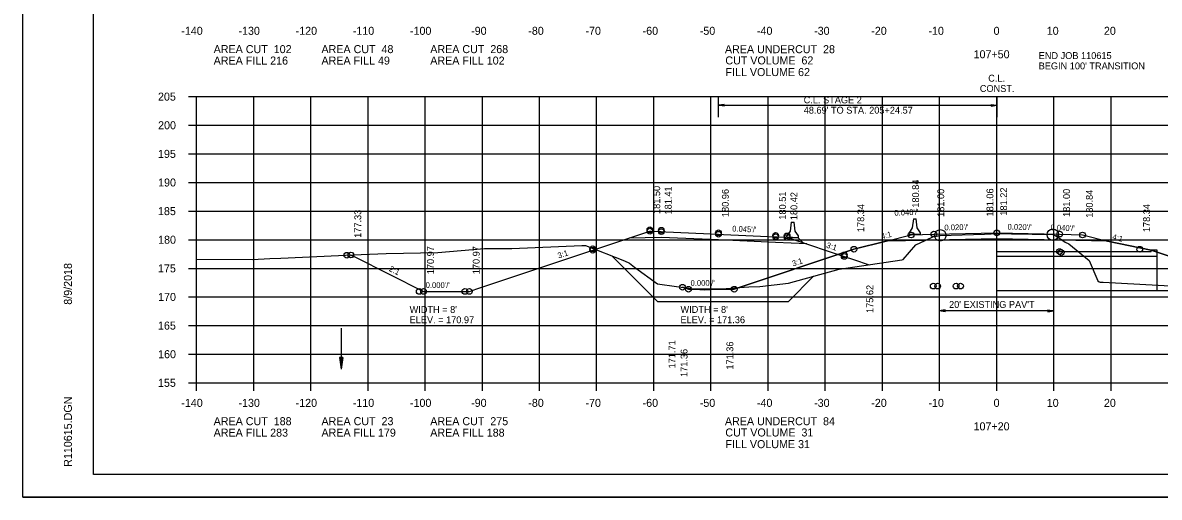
# Model space of a CAD drawing. Extents: x 1372132 to 1372465, y 380083 to 381790.
# Drawn here: x 1372131.6 to 1372330.4, y 380936.8 to 381019.7 of the extents above; entities that cross this region are included whole.
import ezdxf

# ---------------------------------------------------------------- set-up
doc = ezdxf.new("R2010")
doc.units = 0
for name, color, linetype in [('Default', 7, 'Continuous'), ('R_Alt Surface', 7, 'Continuous'), ('R_Axis', 7, 'Continuous'), ('R_Axis Annot', 7, 'Continuous'), ('R_Border', 7, 'Continuous'), ('R_Dimension', 7, 'Continuous'), ('R_Draft', 7, 'Continuous'), ('R_Erosion', 7, 'Continuous'), ('R_Exist Surface', 7, 'Continuous'), ('R_Fin Surface', 7, 'Continuous'), ('R_Grid', 7, 'Continuous'), ('R_No Plot', 7, 'Continuous'), ('R_Xsect Elev', 7, 'Continuous'), ('R_Xsect Slope', 7, 'Continuous')]:
    doc.layers.add(name, color=color, linetype=linetype)

msp = doc.modelspace()

# ---------------------------------------------------------------- linework, layer by layer
at = {"layer": 'Default'}
for p, q in [((1372329.04, 380979.74), (1372302.01, 380979.71)), ((1372329.04, 380979.74), (1372329.04, 380979.99)), ((1372330.04, 380979.99), (1372329.04, 380979.99)), ((1372330.04, 380972.9), (1372330.04, 380979.99)), ((1372330.04, 380978.9), (1372302.01, 380978.88)), ((1372344.25, 380972.92), (1372302.01, 380972.88))]:
    msp.add_line(p, q, dxfattribs=at)
at = {"layer": 'R_Alt Surface'}
for points in [[(1372268.79, 380981.09), (1372263.32, 380981.34), (1372253.32, 380981.79), (1372243.32, 380982.24), (1372237.72, 380982.12)], [(1372321.38, 380981.57), (1372313.01, 380981.74), (1372302.01, 380981.96), (1372291.01, 380981.74), (1372282.65, 380981.57)]]:
    msp.add_lwpolyline(points, dxfattribs=at)
at = {"layer": 'R_Axis'}
for p, q in [((1372160.61, 381006.83), (1372162.01, 381006.83)), ((1372162.01, 380956.83), (1372162.01, 381006.83)), ((1372160.61, 381001.83), (1372162.01, 381001.83)), ((1372160.61, 380996.83), (1372162.01, 380996.83)), ((1372160.61, 380991.83), (1372162.01, 380991.83)), ((1372160.61, 380986.83), (1372162.01, 380986.83)), ((1372160.61, 380981.83), (1372162.01, 380981.83)), ((1372160.61, 380976.83), (1372162.01, 380976.83)), ((1372160.61, 380971.83), (1372162.01, 380971.83)), ((1372160.61, 380966.83), (1372162.01, 380966.83)), ((1372160.61, 380961.83), (1372162.01, 380961.83)), ((1372160.61, 380956.83), (1372162.01, 380956.83)), ((1372162.01, 380956.83), (1372442.01, 380956.83)), ((1372162.01, 380955.43), (1372162.01, 380956.83)), ((1372172.01, 380955.43), (1372172.01, 380956.83)), ((1372182.01, 380955.43), (1372182.01, 380956.83)), ((1372192.01, 380955.43), (1372192.01, 380956.83)), ((1372202.01, 380955.43), (1372202.01, 380956.83)), ((1372212.01, 380955.43), (1372212.01, 380956.83)), ((1372222.01, 380955.43), (1372222.01, 380956.83)), ((1372232.01, 380955.43), (1372232.01, 380956.83)), ((1372242.01, 380955.43), (1372242.01, 380956.83)), ((1372252.01, 380955.43), (1372252.01, 380956.83)), ((1372262.01, 380955.43), (1372262.01, 380956.83)), ((1372272.01, 380955.43), (1372272.01, 380956.83)), ((1372282.01, 380955.43), (1372282.01, 380956.83)), ((1372292.01, 380955.43), (1372292.01, 380956.83)), ((1372302.01, 380955.43), (1372302.01, 380956.83)), ((1372312.01, 380955.43), (1372312.01, 380956.83)), ((1372322.01, 380955.43), (1372322.01, 380956.83))]:
    msp.add_line(p, q, dxfattribs=at)
at = {"layer": 'R_Border'}
for p, q in [((1372144.01, 380940.83), (1372144.01, 381146.29)), ((1372144.01, 380940.83), (1372144.01, 380940.83)), ((1372460.19, 380940.83), (1372144.01, 380940.83))]:
    msp.add_line(p, q, dxfattribs=at)
at = {"layer": 'R_Dimension'}
for p, q in [((1372187.03, 380961.23), (1372187.33, 380959.23)), ((1372187.63, 380961.23), (1372187.03, 380961.23)), ((1372187.03, 380961.23), (1372187.33, 380959.23)), ((1372187.63, 380961.23), (1372187.03, 380961.23)), ((1372187.08, 380961.23), (1372187.33, 380959.56)), ((1372187.08, 380961.23), (1372187.33, 380959.56)), ((1372187.13, 380961.23), (1372187.33, 380959.91)), ((1372187.13, 380961.23), (1372187.33, 380959.91)), ((1372187.18, 380961.23), (1372187.33, 380960.24)), ((1372187.18, 380961.23), (1372187.33, 380960.24)), ((1372187.23, 380961.23), (1372187.33, 380960.58)), ((1372187.23, 380961.23), (1372187.33, 380960.58)), ((1372187.28, 380961.23), (1372187.33, 380960.91)), ((1372187.28, 380961.23), (1372187.33, 380960.91)), ((1372187.63, 380961.23), (1372187.33, 380959.23)), ((1372187.43, 380961.23), (1372187.33, 380960.58)), ((1372187.53, 380961.23), (1372187.33, 380959.91)), ((1372187.58, 380961.23), (1372187.33, 380959.56)), ((1372187.48, 380961.23), (1372187.33, 380960.24)), ((1372187.38, 380961.23), (1372187.33, 380960.91)), ((1372187.63, 380961.23), (1372187.33, 380959.23)), ((1372187.43, 380961.23), (1372187.33, 380960.58)), ((1372187.53, 380961.23), (1372187.33, 380959.91)), ((1372187.58, 380961.23), (1372187.33, 380959.56)), ((1372187.48, 380961.23), (1372187.33, 380960.24)), ((1372187.38, 380961.23), (1372187.33, 380960.91))]:
    msp.add_line(p, q, dxfattribs=at)
at = {"layer": 'R_Draft'}
for p, q in [((1372253.32, 381003.23), (1372253.32, 381006.83)), ((1372302.01, 381006.83), (1372302.01, 381003.23)), ((1372254.32, 381005.46), (1372253.32, 381005.31)), ((1372253.32, 381005.31), (1372302.01, 381005.31)), ((1372254.32, 381005.16), (1372253.32, 381005.31)), ((1372254.32, 381005.44), (1372253.49, 381005.31)), ((1372254.32, 381005.19), (1372253.49, 381005.31)), ((1372254.32, 381005.41), (1372253.66, 381005.31)), ((1372254.32, 381005.21), (1372253.66, 381005.31)), ((1372254.32, 381005.39), (1372253.83, 381005.31)), ((1372254.32, 381005.24), (1372253.83, 381005.31)), ((1372254.32, 381005.36), (1372254, 381005.31)), ((1372254.32, 381005.27), (1372254, 381005.31)), ((1372254.32, 381005.34), (1372254.17, 381005.31)), ((1372254.32, 381005.29), (1372254.17, 381005.31)), ((1372254.32, 381005.16), (1372254.32, 381005.46)), ((1372301.01, 381005.46), (1372302.01, 381005.31)), ((1372301.01, 381005.46), (1372301.01, 381005.16)), ((1372301.01, 381005.46), (1372302.01, 381005.31)), ((1372301.01, 381005.46), (1372301.01, 381005.16)), ((1372301.01, 381005.44), (1372301.85, 381005.31)), ((1372301.01, 381005.44), (1372301.85, 381005.31)), ((1372301.01, 381005.41), (1372301.68, 381005.31)), ((1372301.01, 381005.41), (1372301.68, 381005.31)), ((1372301.01, 381005.39), (1372301.51, 381005.31)), ((1372301.01, 381005.39), (1372301.51, 381005.31)), ((1372301.01, 381005.36), (1372301.34, 381005.31)), ((1372301.01, 381005.36), (1372301.34, 381005.31)), ((1372301.01, 381005.34), (1372301.17, 381005.31)), ((1372301.01, 381005.34), (1372301.17, 381005.31)), ((1372301.01, 381005.16), (1372302.01, 381005.31)), ((1372301.01, 381005.26), (1372301.34, 381005.31)), ((1372301.01, 381005.21), (1372301.68, 381005.31)), ((1372301.01, 381005.19), (1372301.85, 381005.31)), ((1372301.01, 381005.24), (1372301.51, 381005.31)), ((1372301.01, 381005.29), (1372301.17, 381005.31)), ((1372301.01, 381005.16), (1372302.01, 381005.31)), ((1372301.01, 381005.26), (1372301.34, 381005.31)), ((1372301.01, 381005.21), (1372301.68, 381005.31)), ((1372301.01, 381005.19), (1372301.85, 381005.31)), ((1372301.01, 381005.24), (1372301.51, 381005.31)), ((1372301.01, 381005.29), (1372301.17, 381005.31)), ((1372266.05, 380984.91), (1372265.88, 380983.33)), ((1372266.05, 380984.91), (1372266.55, 380984.91)), ((1372266.73, 380983.33), (1372266.55, 380984.91)), ((1372287.23, 380983.89), (1372286.66, 380983.06)), ((1372287.41, 380985.47), (1372287.23, 380983.89)), ((1372287.41, 380985.47), (1372287.91, 380985.47)), ((1372288.09, 380983.89), (1372287.91, 380985.47)), ((1372288.66, 380983.06), (1372288.09, 380983.89)), ((1372265.88, 380983.33), (1372265.3, 380982.49)), ((1372265.3, 380982.24), (1372265.3, 380982.49)), ((1372265.3, 380982.24), (1372267.3, 380982.24)), ((1372267.3, 380982.49), (1372266.73, 380983.33)), ((1372267.3, 380982.24), (1372267.3, 380982.49)), ((1372286.66, 380982.81), (1372286.66, 380983.06)), ((1372286.66, 380982.81), (1372288.66, 380982.81)), ((1372288.66, 380982.81), (1372288.66, 380983.06)), ((1372291.95, 380970.32), (1372291.95, 380968.31)), ((1372311.93, 380970.32), (1372311.93, 380968.55)), ((1372292.95, 380969.56), (1372291.95, 380969.41)), ((1372292.95, 380969.56), (1372291.95, 380969.41)), ((1372311.93, 380969.41), (1372291.95, 380969.41)), ((1372292.95, 380969.26), (1372291.95, 380969.41)), ((1372292.95, 380969.26), (1372291.95, 380969.41)), ((1372291.95, 380968.55), (1372291.95, 380968.55)), ((1372292.95, 380969.53), (1372292.12, 380969.41)), ((1372292.95, 380969.53), (1372292.12, 380969.41)), ((1372292.95, 380969.28), (1372292.12, 380969.41)), ((1372292.95, 380969.28), (1372292.12, 380969.41)), ((1372292.95, 380969.51), (1372292.29, 380969.41)), ((1372292.95, 380969.51), (1372292.29, 380969.41)), ((1372292.95, 380969.31), (1372292.29, 380969.41)), ((1372292.95, 380969.31), (1372292.29, 380969.41)), ((1372292.95, 380969.48), (1372292.46, 380969.41)), ((1372292.95, 380969.48), (1372292.46, 380969.41)), ((1372292.95, 380969.33), (1372292.46, 380969.41)), ((1372292.95, 380969.33), (1372292.46, 380969.41)), ((1372292.95, 380969.45), (1372292.63, 380969.41)), ((1372292.95, 380969.45), (1372292.63, 380969.41)), ((1372292.95, 380969.36), (1372292.63, 380969.41)), ((1372292.95, 380969.36), (1372292.63, 380969.41)), ((1372292.95, 380969.43), (1372292.79, 380969.41)), ((1372292.95, 380969.43), (1372292.79, 380969.41)), ((1372292.95, 380969.38), (1372292.79, 380969.41)), ((1372292.95, 380969.38), (1372292.79, 380969.41)), ((1372292.95, 380969.26), (1372292.95, 380969.56)), ((1372292.95, 380969.26), (1372292.95, 380969.56)), ((1372310.93, 380969.56), (1372311.93, 380969.41)), ((1372310.93, 380969.56), (1372310.93, 380969.26)), ((1372310.93, 380969.53), (1372311.77, 380969.41)), ((1372310.93, 380969.51), (1372311.59, 380969.41)), ((1372310.93, 380969.48), (1372311.43, 380969.41)), ((1372310.93, 380969.45), (1372311.26, 380969.41)), ((1372310.93, 380969.43), (1372311.09, 380969.41)), ((1372310.93, 380969.26), (1372311.93, 380969.41)), ((1372310.93, 380969.36), (1372311.26, 380969.41)), ((1372310.93, 380969.31), (1372311.59, 380969.41)), ((1372310.93, 380969.28), (1372311.77, 380969.41)), ((1372310.93, 380969.33), (1372311.43, 380969.41)), ((1372310.93, 380969.38), (1372311.09, 380969.41)), ((1372187.33, 380966.37), (1372187.33, 380959.23))]:
    msp.add_line(p, q, dxfattribs=at)
at = {"layer": 'R_Erosion'}
for p, q in [((1372267.28, 380982.16), (1372265.32, 380982.25)), ((1372267.28, 380982.16), (1372268.13, 380981.31)), ((1372242.63, 380971.05), (1372234.68, 380979.01)), ((1372265.56, 380971.05), (1372269.97, 380975.46)), ((1372242.63, 380971.05), (1372265.56, 380971.05))]:
    msp.add_line(p, q, dxfattribs=at)
at = {"layer": 'R_Exist Surface'}
msp.add_lwpolyline([(1372162.01, 380978.44), (1372171.82, 380978.4), (1372174.86, 380978.57), (1372176.75, 380978.62), (1372189.34, 380979.17), (1372195.16, 380979.42), (1372204.22, 380979.6), (1372212.39, 380980.29), (1372217.16, 380980.3), (1372229.39, 380980.82), (1372229.92, 380980.84), (1372230.04, 380980.84), (1372236.89, 380978.13), (1372237.73, 380977.76), (1372238.61, 380977.03), (1372242.63, 380974.14), (1372249.33, 380973.22), (1372250.79, 380973.05), (1372254.67, 380973.29), (1372258.61, 380973.6), (1372260.55, 380973.68), (1372265.56, 380974.25), (1372274.41, 380976.67), (1372285.41, 380978.34), (1372285.63, 380978.39), (1372287.87, 380980.93), (1372290.8, 380982.33), (1372291.74, 380982.53), (1372292.13, 380982.59), (1372299.84, 380982.83), (1372302.25, 380982.89), (1372304.58, 380982.85), (1372311.82, 380982.72), (1372312.31, 380982.49), (1372313.98, 380981.42), (1372314.62, 380981.09), (1372318.17, 380978.23), (1372319.68, 380974.67), (1372319.94, 380974.49), (1372320.09, 380974.42), (1372320.59, 380974.4), (1372333.44, 380973.73)], dxfattribs=at)
at = {"layer": 'R_Fin Surface'}
for points in [[(1372189.02, 380979.16), (1372189.69, 380978.82), (1372201.74, 380972.8), (1372202.18, 380972.8), (1372209.74, 380972.8), (1372211.07, 380973.24), (1372231.32, 380979.99), (1372232.05, 380980.23), (1372241.32, 380983.33), (1372241.48, 380983.32), (1372243.32, 380983.24), (1372244.12, 380983.2), (1372253.32, 380982.79), (1372254.19, 380982.75), (1372263.32, 380982.34), (1372263.51, 380982.33), (1372265.32, 380982.25), (1372266.27, 380981.93), (1372275.32, 380978.91), (1372276.93, 380978.38), (1372279.71, 380977.45)], [(1372247.03, 380973.53), (1372248.08, 380973.18), (1372256.08, 380973.18), (1372277.01, 380980.16), (1372282.65, 380981.57), (1372287.01, 380982.66), (1372291.01, 380982.82), (1372302.01, 380983.04), (1372313.01, 380982.82), (1372317.01, 380982.66), (1372321.38, 380981.57), (1372329.04, 380979.99), (1372348.35, 380973.55), (1372352.35, 380973.55), (1372354.28, 380974.19)]]:
    msp.add_lwpolyline(points, dxfattribs=at)
at = {"layer": 'R_Grid'}
for p, q in [((1372162.01, 381006.83), (1372442.01, 381006.83)), ((1372162.01, 380956.83), (1372162.01, 381006.83)), ((1372172.01, 380956.83), (1372172.01, 381006.83)), ((1372182.01, 380956.83), (1372182.01, 381006.83)), ((1372192.01, 380956.83), (1372192.01, 381006.83)), ((1372202.01, 380956.83), (1372202.01, 381006.83)), ((1372212.01, 380956.83), (1372212.01, 381006.83)), ((1372222.01, 380956.83), (1372222.01, 381006.83)), ((1372232.01, 380956.83), (1372232.01, 381006.83)), ((1372242.01, 380956.83), (1372242.01, 381006.83)), ((1372252.01, 380956.83), (1372252.01, 381006.83)), ((1372262.01, 380956.83), (1372262.01, 381006.83)), ((1372272.01, 380956.83), (1372272.01, 381006.83)), ((1372282.01, 380956.83), (1372282.01, 381006.83)), ((1372292.01, 380956.83), (1372292.01, 381006.83)), ((1372302.01, 380956.83), (1372302.01, 381006.83)), ((1372312.01, 380956.83), (1372312.01, 381006.83)), ((1372322.01, 380956.83), (1372322.01, 381006.83)), ((1372162.01, 381001.83), (1372442.01, 381001.83)), ((1372162.01, 380996.83), (1372442.01, 380996.83)), ((1372162.01, 380991.83), (1372442.01, 380991.83)), ((1372162.01, 380986.83), (1372442.01, 380986.83)), ((1372162.01, 380981.83), (1372442.01, 380981.83)), ((1372162.01, 380976.83), (1372442.01, 380976.83)), ((1372162.01, 380971.83), (1372442.01, 380971.83)), ((1372162.01, 380966.83), (1372442.01, 380966.83)), ((1372162.01, 380961.83), (1372442.01, 380961.83)), ((1372162.01, 380956.83), (1372442.01, 380956.83))]:
    msp.add_line(p, q, dxfattribs=at)
at = {"layer": 'R_No Plot'}
msp.add_line((1372131.61, 380936.85), (1372464.95, 380936.85), dxfattribs=at)
for points in [[(1372131.61, 381150.18), (1372464.95, 381150.18), (1372464.95, 380936.84), (1372131.61, 380936.84)], [(1372377.93, 381146.29), (1372377.93, 381136.41), (1372413.67, 381136.41), (1372413.67, 381133.49), (1372436.87, 381133.49), (1372436.87, 381109.15), (1372460.19, 381109.15), (1372460.19, 380940.83), (1372144.01, 380940.83), (1372144.01, 381146.29)], [(1372256.92, 380973.47), (1372258.61, 380973.6), (1372260.55, 380973.68), (1372265.56, 380974.25), (1372274.41, 380976.67), (1372285.41, 380978.34), (1372285.63, 380978.39), (1372287.87, 380980.93), (1372289.49, 380981.71), (1372282.65, 380981.57), (1372277.01, 380980.16)], [(1372289.49, 380981.71), (1372290.8, 380982.33), (1372291.74, 380982.53), (1372292.13, 380982.59), (1372299.84, 380982.83), (1372302.25, 380982.89), (1372304.58, 380982.85), (1372311.82, 380982.72), (1372312.31, 380982.49), (1372313.5, 380981.73), (1372313.01, 380981.74), (1372302.01, 380981.96), (1372291.01, 380981.74)], [(1372313.5, 380981.73), (1372313.98, 380981.42), (1372314.62, 380981.09), (1372318.17, 380978.23), (1372319.68, 380974.67), (1372319.94, 380974.49), (1372320.09, 380974.42), (1372320.59, 380974.4), (1372333.44, 380973.73), (1372336.66, 380973.6), (1372342.14, 380973.75), (1372345.89, 380973.77), (1372346.54, 380973.79), (1372346.82, 380973.8), (1372347.5, 380973.83), (1372329.04, 380979.99), (1372321.38, 380981.57)], [(1372247.03, 380973.53), (1372249.33, 380973.22), (1372249.61, 380973.18), (1372248.08, 380973.18)], [(1372249.61, 380973.18), (1372250.79, 380973.05), (1372252.98, 380973.18)], [(1372252.98, 380973.18), (1372254.67, 380973.29), (1372256.92, 380973.47), (1372256.08, 380973.18)]]:
    msp.add_lwpolyline(points, close=True, dxfattribs=at)
for centre, radius in [((1372241.32, 380983.58), 0.5), ((1372241.32, 380983.33), 0.5), ((1372243.32, 380983.49), 0.5), ((1372243.32, 380983.24), 0.5), ((1372311.82, 380982.72), 1), ((1372253.32, 380983.04), 0.5), ((1372253.32, 380982.79), 0.5), ((1372263.32, 380982.59), 0.5), ((1372263.32, 380982.34), 0.5), ((1372265.32, 380982.5), 0.5), ((1372265.32, 380982.25), 0.5), ((1372287.01, 380982.66), 0.5), ((1372291.01, 380982.82), 0.5), ((1372292.13, 380982.59), 1), ((1372302.01, 380983.04), 0.5), ((1372313.01, 380982.82), 0.5), ((1372317.01, 380982.66), 0.5), ((1372189.02, 380979.16), 0.5), ((1372231.32, 380980.25), 0.5), ((1372231.32, 380979.99), 0.5), ((1372275.32, 380979.17), 0.5), ((1372277.01, 380980.16), 0.5), ((1372312.98, 380979.76), 0.5), ((1372313.27, 380979.6), 0.5), ((1372327.01, 380980.16), 0.5), ((1372188.31, 380979.12), 0.5), ((1372275.32, 380978.91), 0.5), ((1372247.03, 380973.53), 0.5), ((1372248.08, 380973.18), 0.5), ((1372256.08, 380973.18), 0.5), ((1372290.89, 380973.73), 0.5), ((1372291.66, 380973.73), 0.5), ((1372294.89, 380973.73), 0.5), ((1372295.66, 380973.73), 0.5), ((1372200.97, 380972.8), 0.5), ((1372201.74, 380972.8), 0.5), ((1372208.97, 380972.8), 0.5), ((1372209.74, 380972.8), 0.5)]:
    msp.add_circle(centre, radius, dxfattribs=at)
at = {"layer": 'R_Xsect Elev'}
msp.add_line((1372302.01, 380982.89), (1372302.01, 380992.89), dxfattribs=at)

# ---------------------------------------------------------------- texts
at = {"layer": 'R_Axis Annot'}
for s, p in [('-140', (1372159.35, 381017.63)), ('-130', (1372169.35, 381017.63)), ('-120', (1372179.35, 381017.63)), ('-110', (1372189.35, 381017.63)), ('-100', (1372199.35, 381017.63)), ('-90', (1372210.05, 381017.63)), ('-80', (1372220.05, 381017.63)), ('-70', (1372230.05, 381017.63)), ('-60', (1372240.05, 381017.63)), ('-50', (1372250.05, 381017.63)), ('-40', (1372260.05, 381017.63)), ('-30', (1372270.05, 381017.63)), ('-20', (1372280.05, 381017.63)), ('-10', (1372290.05, 381017.63)), ('0', (1372301.45, 381017.63)), ('10', (1372310.75, 381017.63)), ('20', (1372320.75, 381017.63)), ('AREA CUT  102', (1372165.01, 381014.43)), ('AREA CUT  48', (1372183.87, 381014.43)), ('AREA CUT  268', (1372202.9, 381014.43)), ('AREA UNDERCUT  28', (1372254.45, 381014.42)), ('AREA FILL 216', (1372165.01, 381012.43)), ('AREA FILL 49', (1372183.87, 381012.43)), ('AREA FILL 102', (1372202.9, 381012.43)), ('CUT VOLUME  62', (1372254.52, 381012.46)), ('107+50', (1372297.95, 381013.53)), ('FILL VOLUME 62', (1372254.55, 381010.42)), ('205', (1372155.27, 381006.13)), ('200', (1372155.29, 381001.13)), ('195', (1372155.27, 380996.13)), ('190', (1372155.29, 380991.13)), ('185', (1372155.27, 380986.13)), ('180', (1372155.29, 380981.13)), ('175', (1372155.27, 380976.13)), ('170', (1372155.29, 380971.13)), ('165', (1372155.27, 380966.13)), ('160', (1372155.29, 380961.13)), ('155', (1372155.27, 380956.13)), ('-140', (1372159.35, 380952.63)), ('-130', (1372169.35, 380952.63)), ('-120', (1372179.35, 380952.63)), ('-110', (1372189.35, 380952.63)), ('-100', (1372199.35, 380952.63)), ('-90', (1372210.05, 380952.63)), ('-80', (1372220.05, 380952.63)), ('-70', (1372230.05, 380952.63)), ('-60', (1372240.05, 380952.63)), ('-50', (1372250.05, 380952.63)), ('-40', (1372260.05, 380952.63)), ('-30', (1372270.05, 380952.63)), ('-20', (1372280.05, 380952.63)), ('-10', (1372290.05, 380952.63)), ('0', (1372301.45, 380952.63)), ('10', (1372310.75, 380952.63)), ('20', (1372320.75, 380952.63)), ('AREA CUT  188', (1372165.01, 380949.43)), ('AREA CUT  23', (1372183.87, 380949.43)), ('AREA CUT  275', (1372202.9, 380949.43)), ('AREA UNDERCUT  84', (1372254.45, 380949.42)), ('107+20', (1372297.95, 380948.53)), ('AREA FILL 283', (1372165.01, 380947.43)), ('AREA FILL 179', (1372183.87, 380947.43)), ('AREA FILL 188', (1372202.9, 380947.43)), ('CUT VOLUME  31', (1372254.52, 380947.46)), ('FILL VOLUME 31', (1372254.55, 380945.42))]:
    msp.add_text(s, height=1.4, dxfattribs=at).set_placement(p)
at = {"layer": 'R_Border'}
for s, p in [('8/9/2018', (1372140.21, 380970.47)), ('R110615.DGN', (1372140.21, 380942.15))]:
    msp.add_text(s, height=1.4, rotation=90, dxfattribs=at).set_placement(p)
at = {"layer": 'R_Dimension'}
for s, p in [("WIDTH = 8'", (1372199.29, 380969.04)), ("WIDTH = 8'", (1372246.68, 380969.05)), ('ELEV. = 170.97', (1372199.29, 380967.24)), ('ELEV. = 171.36', (1372246.68, 380967.25))]:
    msp.add_text(s, height=1.2, dxfattribs=at).set_placement(p)
at = {"layer": 'R_Draft'}
for s, p in [('END JOB 110615', (1372309.34, 381013.4)), ("BEGIN 100' TRANSITION", (1372309.34, 381011.6)), ('C.L. ', (1372300.51, 381009.45)), ('CONST. ', (1372299.04, 381007.65)), ('C.L. STAGE 2', (1372268.23, 381005.66)), ("48.69' TO STA. 205+24.57", (1372268.23, 381003.86)), ("20' EXISTING PAV'T", (1372293.66, 380969.92))]:
    msp.add_text(s, height=1.2, rotation=360, dxfattribs=at).set_placement(p)
at = {"layer": 'R_Xsect Elev'}
for s, p in [('180.84', (1372288.41, 380987.43)), ('181.50', (1372243.12, 380986.33)), ('181.41', (1372245.12, 380986.24)), ('180.96', (1372255.12, 380985.79)), ('180.51', (1372265.12, 380985.34)), ('180.42', (1372267.12, 380985.25)), ('181.00', (1372292.81, 380985.82)), ('181.06', (1372301.41, 380985.89)), ('181.22', (1372303.81, 380986.04)), ('181.00', (1372314.81, 380985.82)), ('180.84', (1372318.81, 380985.66)), ('178.34', (1372278.81, 380983.16)), ('178.34', (1372328.81, 380983.16)), ('177.33', (1372190.82, 380982.16)), ('170.97', (1372203.54, 380975.8)), ('170.97', (1372211.54, 380975.8)), ('175.62', (1372280.4, 380969.03)), ('171.71', (1372245.78, 380959.35)), ('171.36', (1372255.91, 380959.14)), ('171.36', (1372247.9, 380957.85))]:
    msp.add_text(s, height=1.2, rotation=90, dxfattribs=at).set_placement(p)
at = {"layer": 'R_Xsect Slope'}
for s, rotation, p in [("0.040'/'", 2.2906, (1372284.11, 380986.02)), ("0.045'/'", 357.4235, (1372255.7, 380983.28)), ("0.020'/'", 1.1458, (1372292.85, 380983.46)), ("0.020'/'", 358.8542, (1372303.88, 380983.6)), ("0.040'/'", 357.7094, (1372311.39, 380983.49)), ('4:1', 14.0362, (1372281.89, 380981.9)), ('4:1', 345.9638, (1372322.14, 380981.9)), ('3:1', 18.4347, (1372225.37, 380978.54)), ('3:1', 341.5661, (1372272.09, 380980.48)), ('3:1', 18.4332, (1372266.39, 380977.15)), ('2:1', 333.4319, (1372195.6, 380976.42)), ("0.000'/'", 359.999, (1372202.09, 380973.4)), ("0.000'/'", 360, (1372248.43, 380973.78))]:
    msp.add_text(s, height=1, rotation=rotation, dxfattribs=at).set_placement(p)

doc.saveas('drawing.dxf')
